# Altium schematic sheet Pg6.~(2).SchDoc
size A4; Date: Not shown in title block; ApprovedBy: Not shown in title block; CheckedBy: Not shown in title block; Author: Not shown in title block; CompanyName: Not shown in title block; Engineer: Not shown in title block; Organization: Not shown in title block; Address1: Not shown in title block; Address2: Not shown in title block; Address3: Not shown in title block; Address4: Not shown in title block; DocumentNumber: 6; Revision: Use project parameter SCH_Rev; SheetNumber: 6; SheetTotal: 7; PageSetup: Record=PageOptions|CenterHorizontal=True|CenterVertical=True|PrintScale=1.00|XCorrection=1.00|YCorrection=1.00|PrintKind=0|BorderSize=5000000|LeftOffset=0|BottomOffset=0|Orientation=2|PaperLength=1000|PaperWidth=1000|Scale=100|PaperSource=15|PrintQuality=600|MediaType=1|DitherType=10|PaperKind=Letter|PrintScaleMode=1
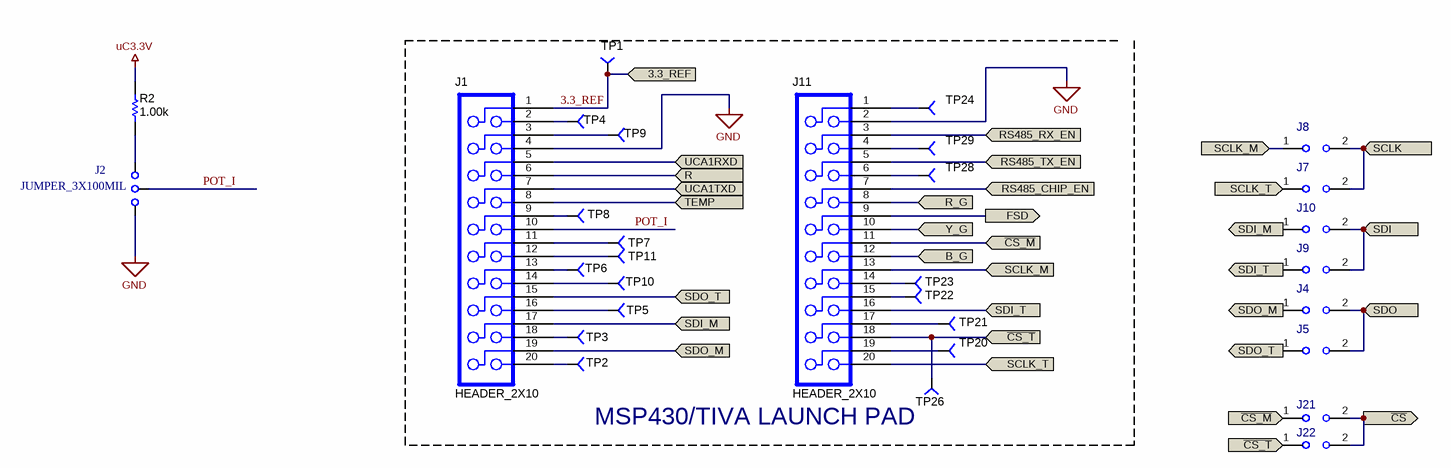
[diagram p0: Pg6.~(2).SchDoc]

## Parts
J1  HEADER_2X10  [HEADER_2X10P]
J2  JUMPER_3X100MIL  [HDR100_1X3]
J4  JUMPER_2X100MIL  [HDR100_1X2]  (value not drawn)
J5  JUMPER_2X100MIL  [HDR100_1X2]  (value not drawn)
J7  JUMPER_2X100MIL  [HDR100_1X2]  (value not drawn)
J8  JUMPER_2X100MIL  [HDR100_1X2]  (value not drawn)
J9  JUMPER_2X100MIL  [HDR100_1X2]  (value not drawn)
J10  JUMPER_2X100MIL  [HDR100_1X2]  (value not drawn)
J11  HEADER_2X10  [HEADER_2X10P]
J21  JUMPER_2X100MIL  [HDR100_1X2]  (value not drawn)
J22  JUMPER_2X100MIL  [HDR100_1X2]  (value not drawn)
R2  value 1.00k  [0805_HV]  (hidden comment: CRCW08051K00FKEA)
TP1  TP-040_RND  [TP-040_RND]  (value not drawn)
TP2  TP-040_RND  [TP-040_RND]  (value not drawn)
TP3  TP-040_RND  [TP-040_RND]  (value not drawn)
TP4  TP-040_RND  [TP-040_RND]  (value not drawn)
TP5  TP-040_RND  [TP-040_RND]  (value not drawn)
TP6  TP-040_RND  [TP-040_RND]  (value not drawn)
TP7  TP-040_RND  [TP-040_RND]  (value not drawn)
TP8  TP-040_RND  [TP-040_RND]  (value not drawn)
TP9  TP-040_RND  [TP-040_RND]  (value not drawn)
TP10  TP-040_RND  [TP-040_RND]  (value not drawn)
TP11  TP-040_RND  [TP-040_RND]  (value not drawn)
TP20  TP-040_RND  [TP-040_RND]  (value not drawn)
TP21  TP-040_RND  [TP-040_RND]  (value not drawn)
TP22  TP-040_RND  [TP-040_RND]  (value not drawn)
TP23  TP-040_RND  [TP-040_RND]  (value not drawn)
TP24  TP-040_RND  [TP-040_RND]  (value not drawn)
TP26  TP-040_RND  [TP-040_RND]  (value not drawn)
TP28  TP-040_RND  [TP-040_RND]  (value not drawn)
TP29  TP-040_RND  [TP-040_RND]  (value not drawn)

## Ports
3.3_REF (in), B_G (in), FSD (out), R, R_G (in), RS485_CHIP_EN (in), RS485_RX_EN (in), RS485_TX_EN (in), SCLK (in), SCLK_M (in), SCLK_T (in), SDI, SDI_M, SDI_T, SDO, SDO_M, SDO_T, TEMP, UCA1RXD, UCA1TXD, Y_G (in), ~{CS_M} (in), ~{CS_T} (in), ~{CS} (in)

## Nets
GND: J1.4 J2.3 J11.2
uC3.3V: R2.2
3.3_REF: J1.1 TP1.1 ; port 3.3_REF
~{CS}: J21.2 J22.2 ; port ~{CS}
~{CS_M}: J11.11 J21.1 ; port ~{CS_M}
~{CS_T}: J11.18 J22.1 TP26.1 ; port ~{CS_T}
B_G: J11.12 ; port B_G
FSD: J11.9 ; port FSD
POT_I: J1.10 J2.2
R: J1.6 ; port R
R_G: J11.8 ; port R_G
RS485_CHIP_EN: J11.7 ; port RS485_CHIP_EN
RS485_RX_EN: J11.3 ; port RS485_RX_EN
RS485_TX_EN: J11.5 ; port RS485_TX_EN
SCLK: J7.2 J8.2 ; port SCLK
SCLK_M: J8.1 J11.13 ; port SCLK_M
SCLK_T: J7.1 J11.20 ; port SCLK_T
SDI: J9.2 J10.2 ; port SDI
SDI_M: J1.17 J10.1 ; port SDI_M
SDI_T: J9.1 J11.16 ; port SDI_T
SDO: J4.2 J5.2 ; port SDO
SDO_M: J1.19 J4.1 ; port SDO_M
SDO_T: J1.15 J5.1 ; port SDO_T
TEMP: J1.8 ; port TEMP
UCA1RXD: J1.5 ; port UCA1RXD
UCA1TXD: J1.7 ; port UCA1TXD
Y_G: J11.10 ; port Y_G
NetJ1_2: J1.2 TP4.1
NetJ1_3: J1.3 TP9.1
NetJ1_9: J1.9 TP8.1
NetJ1_11: J1.11 TP7.1
NetJ1_12: J1.12 TP11.1
NetJ1_13: J1.13 TP6.1
NetJ1_14: J1.14 TP10.1
NetJ1_16: J1.16 TP5.1
NetJ1_18: J1.18 TP3.1
NetJ1_20: J1.20 TP2.1
NetJ2_1: J2.1 R2.1
NetJ11_1: J11.1 TP24.1
NetJ11_4: J11.4 TP29.1
NetJ11_6: J11.6 TP28.1
NetJ11_14: J11.14 TP23.1
NetJ11_15: J11.15 TP22.1
NetJ11_17: J11.17 TP21.1
NetJ11_19: J11.19 TP20.1

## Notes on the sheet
- MSP430/TIVA LAUNCH PAD

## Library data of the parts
J1 J11 = HEADER_2X10: Header, Male 2x10-pin, 100mil spacing; PartNumber: PEC10DAAN; Manufacturer: Sullins; Area: 200000; Value: PEC10DAAN
J2 = JUMPER_3X100MIL: Header, Male 3-pin, 100mil spacing,; Manufacturer: Sullins; PartNumber: PEC03SAAN; area: 30000; Value: PEC03SAAN
J4 J5 J7-J10 J21 J22 = JUMPER_2X100MIL: Header, Male 2-pin, 100mil spacing,; Manufacturer: Sullins; PartNumber: PEC02SAAN; area: 20000; Value: PEC02SAAN
R2 = CRCW08051K00FKEA: RES, 1.00k ohm, 1%, 0.125W, 0805; Manufacturer: Vishay-Dale; CompType: Resistor; Res_ohm: 1000; Value_Code: 1k00; Tolerance_%: 1; Power_W: 0.125; VDC_V: 150; TempCo: 100 ppm/C; EIA_Code: E96; U/M: EA
TP1-TP11 TP20-TP24 TP26 TP28 TP29 = TP-040_RND: Test Point, O.040 Hole; Manufacturer: STD; Value: STD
